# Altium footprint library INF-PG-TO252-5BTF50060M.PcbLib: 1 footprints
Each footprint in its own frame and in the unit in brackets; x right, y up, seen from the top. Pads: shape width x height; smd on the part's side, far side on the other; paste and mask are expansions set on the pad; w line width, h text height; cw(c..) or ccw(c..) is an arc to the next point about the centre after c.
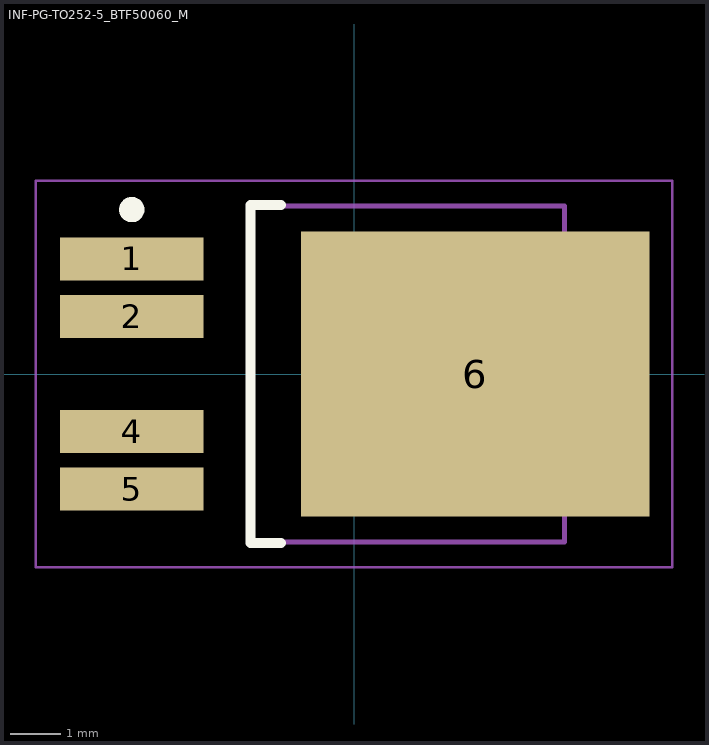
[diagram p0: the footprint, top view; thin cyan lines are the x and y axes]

## INF-PG-TO252-5_BTF50060_M [mm] "DPAK, 5-Leads, Body 6.5x6.12mm, Pitch 1.14mm, IPC Low Density"
height 2.35
pads (5):
  rect 2.85x0.85 smd: 1(-4.4,2.28) 2(-4.4,1.14) 4(-4.4,-1.14) 5(-4.4,-2.28)
  rect 6.9x5.65 smd: 6(2.4,0)
Top Overlay:
  circle w0.25: c-4.4,3.255 r0.125
  lines w0.2: -1.45,-3.35 -2.05,-3.35 -2.05,3.35 -1.45,3.35
Mechanical 13:
  lines w0.1: -2.05,-3.325 -2.05,3.325 4.17,3.325 4.17,-3.325 -2.05,-3.325
Mechanical 15:
  lines w0.05: -6.3,-3.825 -6.3,3.825 6.3,3.825 6.3,-3.825 -6.3,-3.825
  lines w0.1: -0.5,0 0.5,0 ; 0,-0.5 0,0.5
3D body: height 2.35, standoff 0, extent -2.05,-3.325 4.17,3.325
